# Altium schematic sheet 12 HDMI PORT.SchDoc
size 420 x 297 mm
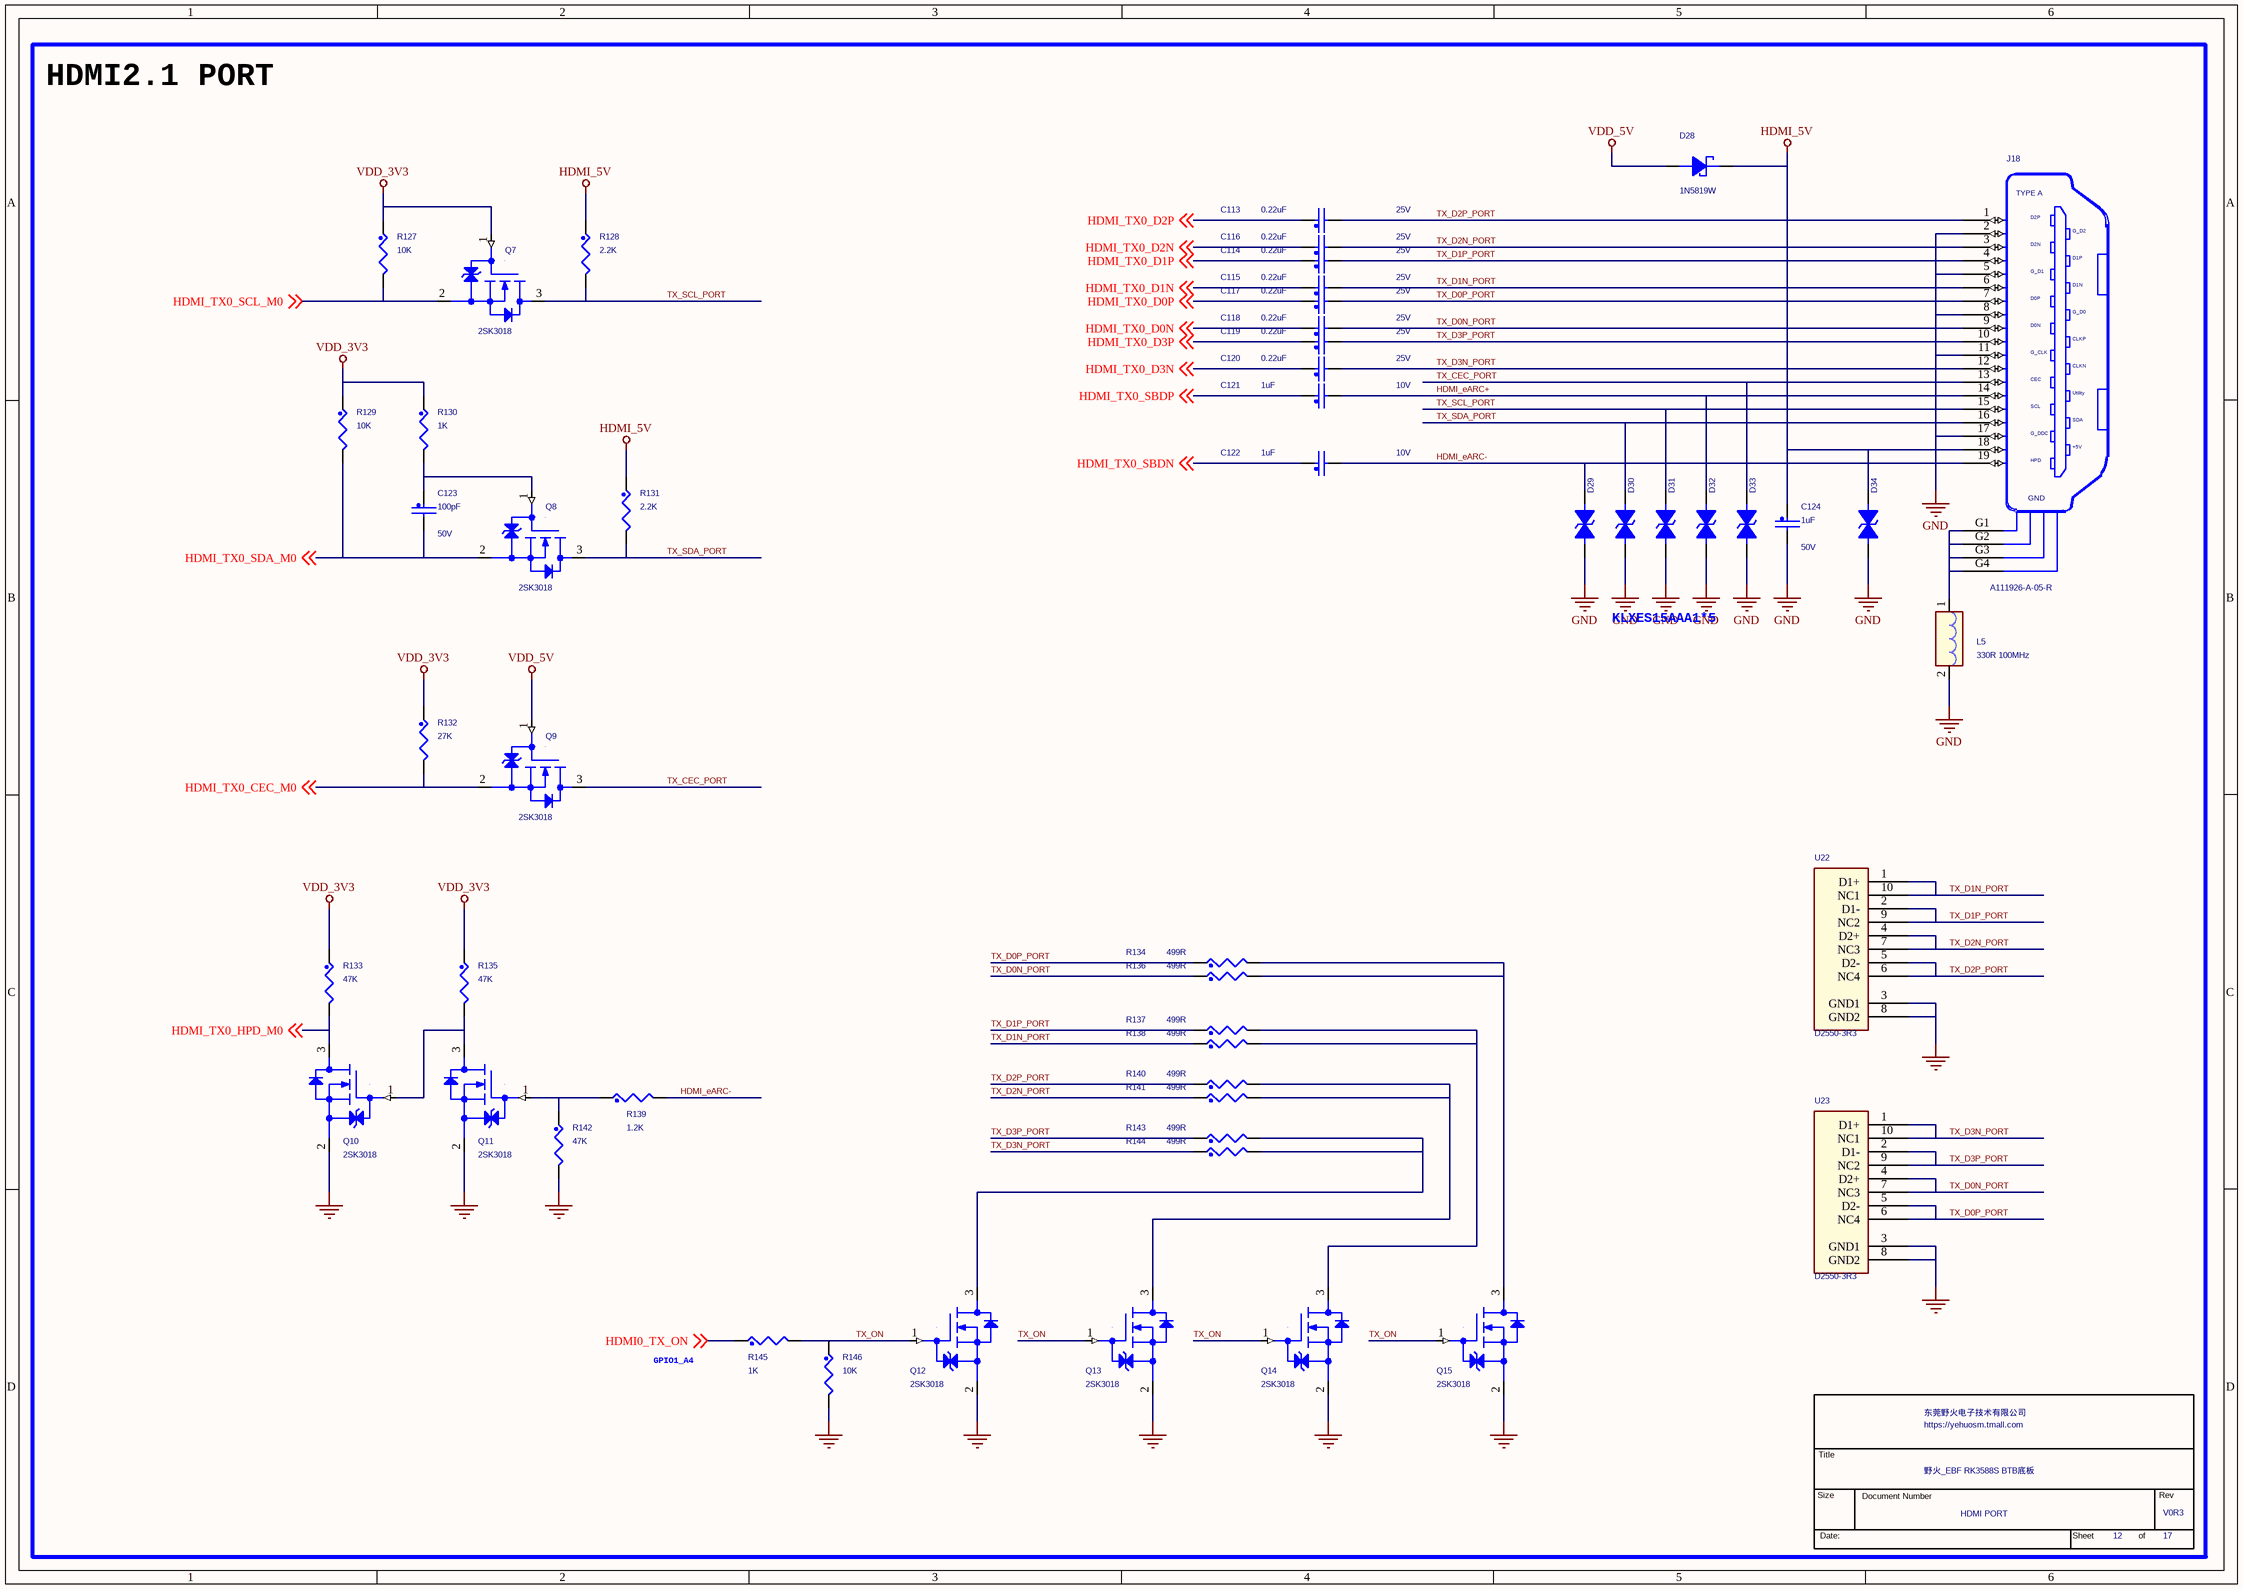
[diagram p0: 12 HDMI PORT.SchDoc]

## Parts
*  Page Count: 17  Page Number: 12  OrgName: 东莞野火电子技术有限公司  Title: 野火_EBF RK3588S BTB底板  RevCode: V0R3  Doc: HDMI PORT  (hidden comment: TitleBlock_YHSCH)  (graphical)
C113  0.22uF  Voltage: 25V  [C0402]
C114  0.22uF  Voltage: 25V  [C0402]
C115  0.22uF  Voltage: 25V  [C0402]
C116  0.22uF  Voltage: 25V  [C0402]
C117  0.22uF  Voltage: 25V  [C0402]
C118  0.22uF  Voltage: 25V  [C0402]
C119  0.22uF  Voltage: 25V  [C0402]
C120  0.22uF  Voltage: 25V  [C0402]
C121  1uF  Voltage: 10V  [C0402]
C122  1uF  Voltage: 10V  [C0402]
C123  100pF  Voltage: 50V  [C0402]
C124  1uF  Voltage: 50V  [C0603]
D28  1N5819W  [SOD-123]
D29  KLXES15AAA1  [D0603/SMD]  (value not drawn)
D30  KLXES15AAA1  [D0603/SMD]  (value not drawn)
D31  KLXES15AAA1  [D0603/SMD]  (value not drawn)
D32  KLXES15AAA1  [D0603/SMD]  (value not drawn)
D33  KLXES15AAA1  [D0603/SMD]  (value not drawn)
D34  KLXES15AAA1  [D0603/SMD]  (value not drawn)
J18  A111926-A-05-R  [hdmi_19f_0p4_bsf-2-c]
L5  330R 100MHz  [L0603]
Q7  2SK3018  [SOT23]
Q8  2SK3018  [SOT23]
Q9  2SK3018  [SOT23]
Q10  2SK3018  [SOT23]
Q11  2SK3018  [SOT23]
Q12  2SK3018  [SOT23]
Q13  2SK3018  [SOT23]
Q14  2SK3018  [SOT23]
Q15  2SK3018  [SOT23]
R127  10K  [R0402]
R128  2.2K  [R0402]
R129  10K  [R0402]
R130  1K  [R0402]
R131  2.2K  [R0402]
R132  27K  [R0402]
R133  47K  [R0402]
R134  499R  [R0402]
R135  47K  [R0402]
R136  499R  [R0402]
R137  499R  [R0402]
R138  499R  [R0402]
R139  1.2K  [R0402]
R140  499R  [R0402]
R141  499R  [R0402]
R142  47K  [R0402]
R143  499R  [R0402]
R144  499R  [R0402]
R145  1K  [R0402]
R146  10K  [R0402]
U22  D2550-3R3  [son10_2r50x1r00x0r50]
U23  D2550-3R3  [son10_2r50x1r00x0r50]

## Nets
GND: C124.2 D29.1 D30.1 D31.1 D32.1 D33.1 D34.1 J18.2(D2GND) J18.5(D1GND) J18.8(D0GND) J18.11(CKGND) J18.17(DDCGND) L5.2 Q10.2(SOURCE) Q11.2(SOURCE) Q12.2(SOURCE) Q13.2(SOURCE) Q14.2(SOURCE) Q15.2(SOURCE) R142.2 R146.2 U22.3(GND1) U22.8(GND2) U23.3(GND1) U23.8(GND2)
HDMI_5V: C124.1 D28.1 D34.2 J18.18(+5V) R128.1 R131.1
VDD_3V3: Q7.1(GATE) R127.1 R129.1 R130.1 R132.1 R133.1 R135.1
VDD_5V: D28.2 Q9.1(GATE)
HDMI0_TX_ON: R145.1 ; off-sheet HDMI0_TX_ON
HDMI_eARC+: C121.2 D32.2 J18.14(Utility)
HDMI_eARC-: C122.2 D29.2 J18.19(HPD) R139.2
HDMI_TX0_CEC_M0: Q9.2(SOURCE) R132.2 ; off-sheet HDMI_TX0_CEC_M0
HDMI_TX0_D0N: C118.1 ; off-sheet HDMI_TX0_D0N
HDMI_TX0_D0P: C117.1 ; off-sheet HDMI_TX0_D0P
HDMI_TX0_D1N: C115.1 ; off-sheet HDMI_TX0_D1N
HDMI_TX0_D1P: C114.1 ; off-sheet HDMI_TX0_D1P
HDMI_TX0_D2N: C116.1 ; off-sheet HDMI_TX0_D2N
HDMI_TX0_D2P: C113.1 ; off-sheet HDMI_TX0_D2P
HDMI_TX0_D3N: C120.1 ; off-sheet HDMI_TX0_D3N
HDMI_TX0_D3P: C119.1 ; off-sheet HDMI_TX0_D3P
HDMI_TX0_HPD_M0: Q10.3(DRAIN) R133.2 ; off-sheet HDMI_TX0_HPD_M0
HDMI_TX0_SBDN: C122.1 ; off-sheet HDMI_TX0_SBDN
HDMI_TX0_SBDP: C121.1 ; off-sheet HDMI_TX0_SBDP
HDMI_TX0_SCL_M0: Q7.2(SOURCE) R127.2 ; off-sheet HDMI_TX0_SCL_M0
HDMI_TX0_SDA_M0: C123.2 Q8.2(SOURCE) R129.2 ; off-sheet HDMI_TX0_SDA_M0
TX_CEC_PORT: D33.2 J18.13(CEC) Q9.3(DRAIN)
TX_D0N_PORT: C118.2 J18.9(D0-) R136.1 U23.4(D2+) U23.7(NC3)
TX_D0P_PORT: C117.2 J18.7(D0+) R134.1 U23.5(D2-) U23.6(NC4)
TX_D1N_PORT: C115.2 J18.6(D1-) R138.1 U22.1(D1+) U22.10(NC1)
TX_D1P_PORT: C114.2 J18.4(D1+) R137.1 U22.2(D1-) U22.9(NC2)
TX_D2N_PORT: C116.2 J18.3(D2-) R141.1 U22.4(D2+) U22.7(NC3)
TX_D2P_PORT: C113.2 J18.1(D2+) R140.1 U22.5(D2-) U22.6(NC4)
TX_D3N_PORT: C120.2 J18.12(CK-) R144.1 U23.1(D1+) U23.10(NC1)
TX_D3P_PORT: C119.2 J18.10(CK+) R143.1 U23.2(D1-) U23.9(NC2)
TX_ON: Q12.1(GATE) Q13.1(GATE) Q14.1(GATE) Q15.1(GATE) R145.2 R146.1
TX_SCL_PORT: D31.2 J18.15(SCL) Q7.3(DRAIN) R128.2
TX_SDA_PORT: D30.2 J18.16(SDA) Q8.3(DRAIN) R131.2
NetC123_1: C123.1 Q8.1(GATE) R130.2
NetJ18_G1: J18.G1(GND1) J18.G2(GND2) J18.G3(GND3) J18.G4(GND4) L5.1
NetQ10_1: Q10.1(GATE) Q11.3(DRAIN) R135.2
NetQ11_1: Q11.1(GATE) R139.1 R142.1
NetQ12_3: Q12.3(DRAIN) R143.2 R144.2
NetQ13_3: Q13.3(DRAIN) R140.2 R141.2
NetQ14_3: Q14.3(DRAIN) R137.2 R138.2
NetQ15_3: Q15.3(DRAIN) R134.2 R136.2

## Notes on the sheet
- HDMI2.1 PORT
- KLXES15AAA1*5
- (near R145) GPIO1_A4

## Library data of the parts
* = TitleBlock_YHSCH: Cage Code: 1
C113-C120 = CAP_NP: CLASS: DISCRETE; 生命周期: 量产; 价格: 0.0073; 规格书: CCTC_TCC0402X5R105K6R3AT; 类别: 贴片电容0402; 品牌: CCTC; 条码: EBFCIS241220094109; 规格编号: TCC0402X7R224K250AT; 规格: 贴片电容0.22uF 20% 25V X7R 0402; 备注: 新增0402物料
C121 = CAP_NP: CLASS: DISCRETE; 规格: 贴片电容1uF 10% 10V X5R 0402; 规格编号: 0402X105K100NT; 条码: EBF29060121; 品牌: 风华; 类别: 贴片电容0402; 规格书: 风华电容.pdf; 价格: 0.01191; 生命周期: 量产
C122 = CAP_NP: CLASS: DISCRETE; 生命周期: 量产; 价格: 0.01191; 规格书: 风华电容.pdf; 类别: 贴片电容0402; 品牌: 风华; 条码: EBF29060121; 规格编号: 0402X105K100NT; 规格: 贴片电容1uF 10% 10V X5R 0402
C123 = CAP_NP: CLASS: DISCRETE; 规格: 贴片电容100pF 5% 50V C0G 0402; 规格编号: GRT1555C1H101JA; 条码: EBF29060302; 品牌: 村田; 类别: 贴片电容0402; 规格书: 村田040系列贴片电容.pdf; 价格: 0.034837; 生命周期: 量产
C124 = CAP_NP: CLASS: DISCRETE; 规格: 贴片电容1uF 10% 50V X7R 0603; 规格编号: 0603B105K500NT; 条码: EBF29060168; 品牌: 风华; 类别: 贴片电容0603; 规格书: 风华电容.pdf; 价格: 0.099678; 生命周期: 量产
D28 = DIODE_SCHTKY: CLASS: IC; 丝印: SL; 生命周期: 量产; 价格: 0.175675; 规格书: 1N5819W.pdf; 类别: 贴片肖特基二极管; 品牌: 台湾迪嘉; 条码: EBF29140016; 规格: 肖特基二极管 直流反向耐压40V 平均整流电流1A 正向压降0.6V@1A SOD-123
D29-D31 D33 = DIODE BI-DIR TRIG: 生命周期: 量产; 价格: 0.09719; 规格书: KLXES15AAA1.pdf; 类别: 贴片ESD; 品牌: 永裕泰; 条码: EBF29140063; 规格: 用于 USB3.0、HDMI 0.5pF、5V、±15kV ESD 保护二极管
D32 D34 = DIODE BI-DIR TRIG: 规格: 用于 USB3.0、HDMI 0.5pF、5V、±15kV ESD 保护二极管; 条码: EBF29140063; 品牌: 永裕泰; 类别: 贴片ESD; 规格书: KLXES15AAA1.pdf; 价格: 0.09719; 生命周期: 量产
J18 = A111926-A-05-R: CLASS: IO; OriginalSymbolOrigin: (-200,650); Vendor: Comtek; VPN: 1166-2C105-211; 规格: HDMI_19P母座 额定电压40V 接触电阻10毫欧 卧贴; 条码: EBF29040046; 品牌: 泰康; 类别: HDMI连接器; 规格书: TECONN(泰康)_HDMI.pdf; 价格: 1.6342; 生命周期: 量产
L5 = BEAD: CLASS: DISCRETE; 生命周期: 量产; 规格书: TDK-MPZ1608S331ATA00.pdf; 类别: 贴片磁珠0603; 品牌: TDK; 条码: EBF29050003; 规格编号: MPZ1608S331ATA00; 规格: 磁珠330Ω @100MHz 额定电流1.7A 直流电阻80mΩ
Q7 Q9-Q13 = 2SK3018: CLASS: IC; 丝印: KN; 生命周期: 量产; 价格: 0.120725; 规格书: 长电科技-2SK3018.pdf; 类别: N-MOS; 品牌: 江苏长电; 条码: EBF29280009; 规格: N沟道MOS 导通电阻8Ω 电流10mA 0.8V可驱动
Q8 Q14 Q15 = 2SK3018: CLASS: IC; 规格: N沟道MOS 导通电阻8Ω 电流10mA 0.8V可驱动; 条码: EBF29280009; 品牌: 江苏长电; 类别: N-MOS; 规格书: 长电科技-2SK3018.pdf; 价格: 0.120725; 生命周期: 量产; 丝印: KN
R127 = RES: CLASS: DISCRETE; 价格: 0.002773; 规格: 贴片电阻10K 1% 1/16W 0402; 规格编号: 0402WGF1002TCE; 条码: EBF29070046; 品牌: 厚声; 类别: 贴片电阻0402; 规格书: 厚声-无铅厚膜电阻.pdf; 生命周期: 量产
R128 = RES: CLASS: DISCRETE; 规格: 贴片电阻2.2K 1% 1/16W 0402; 规格编号: RI0402L2201FT; 条码: EBF29070051; 品牌: 合科泰; 类别: 贴片电阻0402; 规格书: 合科泰-RI系列电阻.pdf; 生命周期: 量产
R129 = RES: CLASS: DISCRETE; 规格: 贴片电阻10K 1% 1/16W 0402; 规格编号: 0402WGF1002TCE; 条码: EBF29070046; 品牌: 厚声; 类别: 贴片电阻0402; 规格书: 厚声-无铅厚膜电阻.pdf; 生命周期: 量产; 价格: 0.002773
R130 R145 = RES: CLASS: DISCRETE; 规格: 贴片电阻1K 1% 1/16W 0402; 规格编号: RI0402L1001FT; 条码: EBF29070050; 品牌: 合科泰; 类别: 贴片电阻0402; 规格书: 合科泰-RI系列电阻.pdf; 生命周期: 量产
R131 = RES: CLASS: DISCRETE; 生命周期: 量产; 规格书: 合科泰-RI系列电阻.pdf; 类别: 贴片电阻0402; 品牌: 合科泰; 条码: EBF29070051; 规格编号: RI0402L2201FT; 规格: 贴片电阻2.2K 1% 1/16W 0402
R132 = RES: CLASS: DISCRETE; 规格: 贴片电阻27K 1% 1/16W 0402; 规格编号: AC0402FR-0727KL; 条码: EBF29070003; 品牌: 国巨; 类别: 贴片电阻0402; 规格书: YAGEO国巨厚膜无铅电阻.pdf; 生命周期: 量产; 价格: 0.007054
R133 R135 = RES: CLASS: DISCRETE; 规格: 贴片电阻47K 1% 1/16W 0402; 规格编号: 0402WGF4702TCE; 条码: EBF29070247; 品牌: 厚声; 类别: 贴片电阻0402; 规格书: 厚声-无铅厚膜电阻.pdf; 生命周期: 量产
R134 R136 R140 R141 = RES: CLASS: DISCRETE; 规格: 贴片电阻499R 1% 1/16W 0402; 规格编号: 0402WGF4990TCE; 条码: EBF29070287; 品牌: 厚声; 类别: 贴片电阻0402; 规格书: 厚声-无铅厚膜电阻.pdf; 价格: 0.003791; 生命周期: 量产
R137 R138 R143 R144 = RES: CLASS: DISCRETE; 生命周期: 量产; 价格: 0.003791; 规格书: 厚声-无铅厚膜电阻.pdf; 类别: 贴片电阻0402; 品牌: 厚声; 条码: EBF29070287; 规格编号: 0402WGF4990TCE; 规格: 贴片电阻499R 1% 1/16W 0402
R139 = RES: CLASS: DISCRETE; 生命周期: 量产; 价格: 0.001447; 规格书: 厚声-无铅厚膜电阻.pdf; 类别: 贴片电阻0402; 品牌: 厚声; 条码: EBFCIS221112112140; 规格编号: 0402WGF1201TCE; 规格: 贴片电阻1.2K 1% 1/16W 0402
R142 = RES: CLASS: DISCRETE; 生命周期: 量产; 规格书: 厚声-无铅厚膜电阻.pdf; 类别: 贴片电阻0402; 品牌: 厚声; 条码: EBF29070247; 规格编号: 0402WGF4702TCE; 规格: 贴片电阻47K 1% 1/16W 0402
R146 = RES: CLASS: DISCRETE; 规格: 贴片电阻10K 1% 1/16W 0402; 规格编号: 0402WGF1002TCE; 条码: EBF29070046; 品牌: 厚声; 类别: 贴片电阻0402; 规格书: 厚声-无铅厚膜电阻.pdf; 价格: 0.002773; 生命周期: 量产
U22 = RCLAMP0524P: 规格: 用于 USB3.0、HDMI2.1和高速接口的四路0.13pF、3.3V、±12kV ESD 保护二极管; 条码: EBFCIS231110170954; 品牌: 千虹; 类别: 贴片四路ESD; 规格书: 千虹_D2550-3R3.pdf; 生命周期: 量产; 备注: 猫5 HDMI2.1新物料; 丝印: 3324P
U23 = RCLAMP0524P: 丝印: 3324P; 备注: 猫5 HDMI2.1新物料; 生命周期: 量产; 规格书: 千虹_D2550-3R3.pdf; 类别: 贴片四路ESD; 品牌: 千虹; 条码: EBFCIS231110170954; 规格: 用于 USB3.0、HDMI2.1和高速接口的四路0.13pF、3.3V、±12kV ESD 保护二极管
